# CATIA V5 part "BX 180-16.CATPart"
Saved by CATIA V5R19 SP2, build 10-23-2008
Part number: BX 180-16
Bounding box of the stored display mesh (mm): x -24.865 to 24.865, y -24.997 to 24.997, z 0 to 106
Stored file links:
  C:\Users\Bora\Desktop\3D Katı model\BX serisi\BX 180\BX 180-16.CATPart
  C:\Program Files\Dassault Systemes\B19\intel_a\reffiles\standard\MetricThickPitch.txt
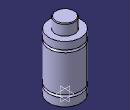
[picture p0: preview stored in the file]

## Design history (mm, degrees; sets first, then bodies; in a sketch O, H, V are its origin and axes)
Body1 (main body)
  Sketch1 on yz-plane, origin (0, 0, 0), H (0, 1, 0), V (0, 0, 1)
    point P2 (25, 12.5)
    line L1 (25, 12.5) -> (25, 0)
    point P3 (25, 16.5)
    point P4 (25, 73.5)
    line L2 (25, 73.5) -> (25, 16.5)
    point P6 (15, 105)
    arc A1 centre (14, 105) radius 1 from (15, 105) to (14, 106) ccw
    point P8 (15, 105)
    line L3 (15, 105) -> (15, 89)
    point P9 (25, 77.5)
    line L4 (25, 89) -> (25, 77.5)
    point P11 (25, 73.5)
    point P12 (25, 77.5)
    arc A2 centre (25, 75.5) radius 2 from (25, 77.5) to (25, 73.5) ccw
    point P13 (25, 12.5)
    point P14 (25, 16.5)
    arc A3 centre (25, 14.5) radius 2 from (25, 16.5) to (25, 12.5) ccw
    line L5 (14, 106) -> (0, 106)
    line L6 (15, 89) -> (25, 89)
    line L7 (25, 0) -> (0, 0)
    tangency: L5 A1
    horizontal: L6 H, L7 H
    coincidence: P2 P13, P3 P14, P4 P11, P6 P8, P9 P12
  Shaft1: profile Sketch1, axis Sketch1.V, angle 360
  Sketch2 on face of Shaft1 from Sketch1.L7, origin (0, 0, 0), H (1, 0, 0), V (0, -1, 0)
    point P1 (12.5, 0)
    distance P1 V = 12.5
  Hole1: placed by Sketch2, at (12.5, 0, 0) direction (0, 0, 1), diameter 4.917, depth 6, threaded "M6", thread diameter 6, thread depth 6, pitch 1
  Sketch3 on face of Shaft1 from Sketch1.L7, origin (0, 0, 0), H (1, 0, 0), V (0, -1, 0)
    point P1 (-12.5, 0)
    distance P1 V = 12.5
  Hole2: placed by Sketch3, at (-12.5, 0, 0) direction (0, 0, 1), diameter 4.917, depth 6, threaded "M6", thread diameter 6, thread depth 6, pitch 1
